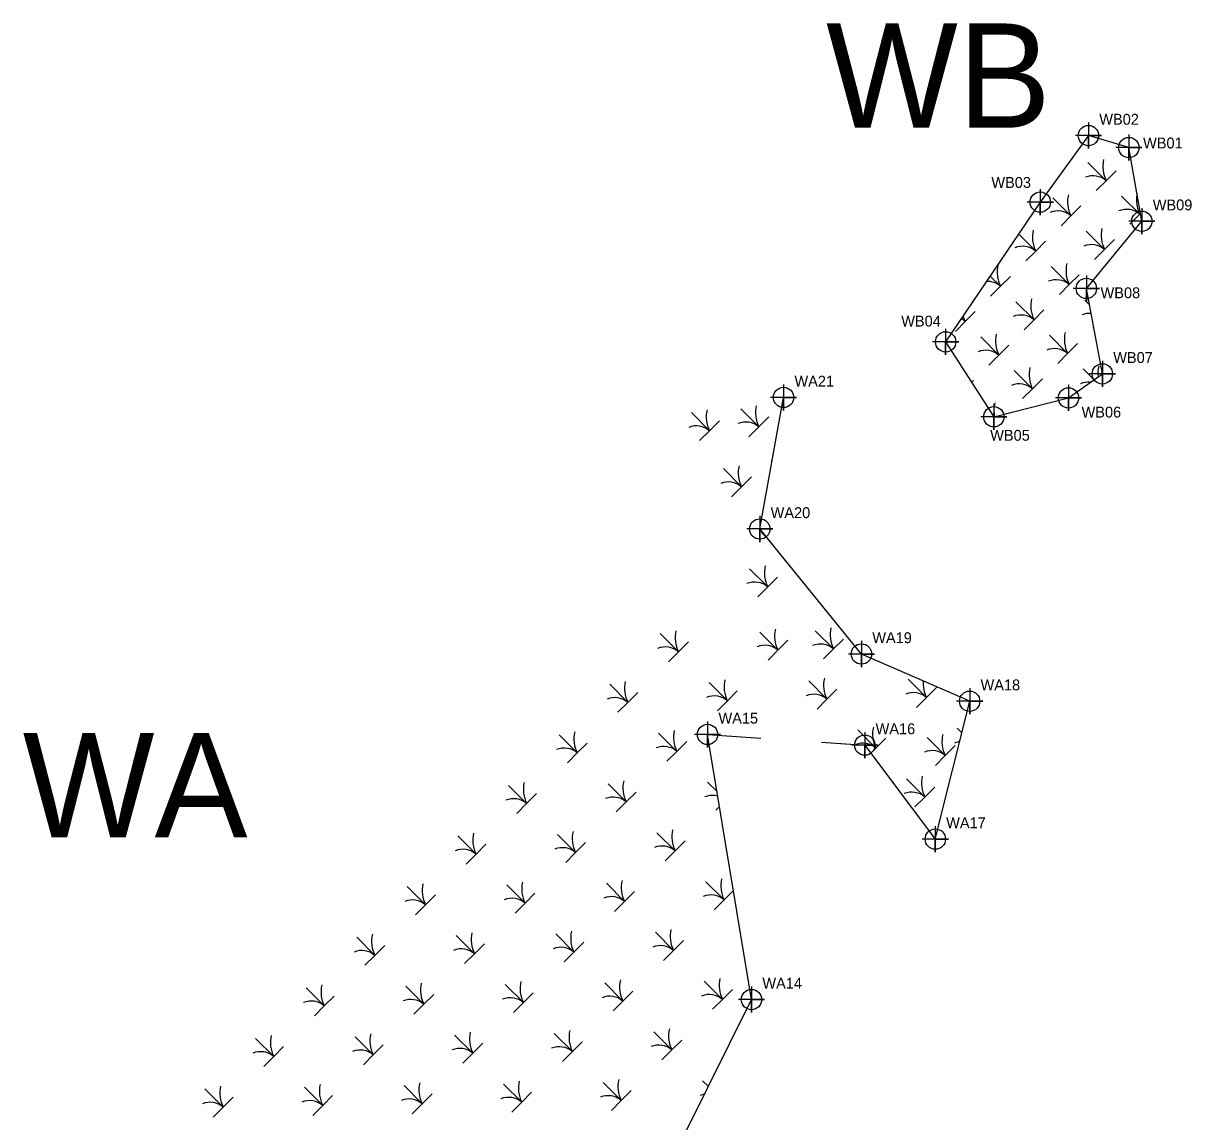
# Model space of a CAD drawing. Extents: x 2129042 to 2129395, y 148168 to 148691.
# Drawn here: x 2129065.6 to 2129334.3, y 148438.5 to 148691.1 of the extents above; entities that cross this region are included whole.
import ezdxf

# ---------------------------------------------------------------- set-up
doc = ezdxf.new("R2010")
doc.units = 0
for name, color, linetype in [('Default', 7, 'Continuous'), ('Exist Environmental Wetland Boundary', 7, 'Continuous'), ('Exist Environmental Wetland Boundary Cogo Number', 7, 'Continuous'), ('Exist Environmental Wetland Boundary Cogo Point CELL', 7, 'Continuous'), ('Exist Hydro Swamp or Marsh', 7, 'Continuous')]:
    doc.layers.add(name, color=color, linetype=linetype)

msp = doc.modelspace()

# ---------------------------------------------------------------- linework, layer by layer
at = {"layer": 'Exist Environmental Wetland Boundary'}
for points in [[(2129319.82, 148662.51), (2129310.52, 148665.27), (2129299.46, 148649.97), (2129277.7, 148617.83), (2129288.78, 148600.6), (2129305.94, 148604.95), (2129313.73, 148610.48), (2129310.05, 148630.13), (2129322.82, 148645.57), (2129319.82, 148662.51)], [(2129249.16, 148525.79), (2129259.09, 148525.12), (2129275.32, 148503.5), (2129283.22, 148535.2), (2129258.32, 148546.06), (2129234.95, 148574.81), (2129240.43, 148605.05)], [(2129099.03, 148321.24), (2129167.08, 148363.39), (2129197.64, 148395.26), (2129233.05, 148466.61), (2129222.96, 148527.56), (2129235.22, 148526.74)]]:
    msp.add_lwpolyline(points, dxfattribs=at)
at = {"layer": 'Exist Environmental Wetland Boundary Cogo Point CELL'}
for points in [[(2129310.52, 148668.27), (2129310.52, 148662.27), (2129310.52, 148665.27), (2129313.52, 148665.27), (2129307.52, 148665.27)], [(2129319.82, 148665.51), (2129319.82, 148659.51), (2129319.82, 148662.51), (2129322.82, 148662.51), (2129316.82, 148662.51)], [(2129299.46, 148652.97), (2129299.46, 148646.97), (2129299.46, 148649.97), (2129302.46, 148649.97), (2129296.46, 148649.97)], [(2129322.82, 148648.57), (2129322.82, 148642.57), (2129322.82, 148645.57), (2129325.82, 148645.57), (2129319.82, 148645.57)], [(2129310.05, 148633.13), (2129310.05, 148627.13), (2129310.05, 148630.13), (2129313.05, 148630.13), (2129307.05, 148630.13)], [(2129277.7, 148620.83), (2129277.7, 148614.83), (2129277.7, 148617.83), (2129280.7, 148617.83), (2129274.7, 148617.83)], [(2129313.73, 148613.48), (2129313.73, 148607.48), (2129313.73, 148610.48), (2129316.73, 148610.48), (2129310.73, 148610.48)], [(2129240.43, 148608.05), (2129240.43, 148602.05), (2129240.43, 148605.05), (2129243.43, 148605.05), (2129237.43, 148605.05)], [(2129305.94, 148607.95), (2129305.94, 148601.95), (2129305.94, 148604.95), (2129308.94, 148604.95), (2129302.94, 148604.95)], [(2129288.78, 148603.6), (2129288.78, 148597.6), (2129288.78, 148600.6), (2129291.78, 148600.6), (2129285.78, 148600.6)], [(2129234.95, 148577.81), (2129234.95, 148571.81), (2129234.95, 148574.81), (2129237.95, 148574.81), (2129231.95, 148574.81)], [(2129258.32, 148549.06), (2129258.32, 148543.06), (2129258.32, 148546.06), (2129261.32, 148546.06), (2129255.32, 148546.06)], [(2129283.22, 148538.2), (2129283.22, 148532.2), (2129283.22, 148535.2), (2129286.22, 148535.2), (2129280.22, 148535.2)], [(2129222.96, 148530.56), (2129222.96, 148524.56), (2129222.96, 148527.56), (2129225.96, 148527.56), (2129219.96, 148527.56)], [(2129259.09, 148528.12), (2129259.09, 148522.12), (2129259.09, 148525.12), (2129262.09, 148525.12), (2129256.09, 148525.12)], [(2129275.32, 148506.5), (2129275.32, 148500.5), (2129275.32, 148503.5), (2129278.32, 148503.5), (2129272.32, 148503.5)], [(2129233.05, 148469.61), (2129233.05, 148463.61), (2129233.05, 148466.61), (2129236.05, 148466.61), (2129230.05, 148466.61)]]:
    msp.add_lwpolyline(points, dxfattribs=at)
for centre in [(2129310.52, 148665.27), (2129319.82, 148662.51), (2129299.46, 148649.97), (2129322.82, 148645.57), (2129310.05, 148630.13), (2129277.7, 148617.83), (2129313.73, 148610.48), (2129240.43, 148605.05), (2129305.94, 148604.95), (2129288.78, 148600.6), (2129234.95, 148574.81), (2129258.32, 148546.06), (2129283.22, 148535.2), (2129222.96, 148527.56), (2129259.09, 148525.12), (2129275.32, 148503.5), (2129233.05, 148466.61)]:
    msp.add_circle(centre, 2.34, dxfattribs=at)
at = {"layer": 'Exist Hydro Swamp or Marsh'}
for p, q in [((2129311.57, 148620.99), (2129311.73, 148621.15)), ((2129283.68, 148608.54), (2129284.12, 148608.98)), ((2129237.61, 148590.44), (2129237.82, 148590.64)), ((2129224.85, 148510.14), (2129225.7, 148510.99))]:
    msp.add_line(p, q, dxfattribs=at)
for points in [[(2129312.32, 148652.62), (2129314.61, 148654.9), (2129310.42, 148659.09), (2129314.61, 148654.9), (2129316.89, 148657.18)], [(2129304.23, 148644.52), (2129306.51, 148646.8), (2129302.32, 148650.99), (2129306.51, 148646.8), (2129308.79, 148649.09)], [(2129320.04, 148644.9), (2129322.33, 148647.18), (2129318.14, 148651.37), (2129322.33, 148647.18), (2129322.5, 148647.36)], [(2129296.13, 148636.43), (2129298.41, 148638.71), (2129294.49, 148642.63)], [(2129294.49, 148642.63), (2129298.41, 148638.71), (2129300.69, 148640.99)], [(2129311.95, 148636.8), (2129314.23, 148639.08), (2129310.04, 148643.27), (2129314.23, 148639.08), (2129316.51, 148641.37)], [(2129303.85, 148628.71), (2129306.13, 148630.99), (2129301.95, 148635.17), (2129306.13, 148630.99), (2129308.41, 148633.27)], [(2129288.03, 148628.33), (2129290.31, 148630.61), (2129287.95, 148632.97)], [(2129287.95, 148632.97), (2129290.31, 148630.61), (2129292.59, 148632.89)], [(2129295.75, 148620.61), (2129298.03, 148622.89), (2129293.85, 148627.07), (2129298.03, 148622.89), (2129300.31, 148625.17)], [(2129310.75, 148626.37), (2129309.67, 148627.45), (2129310.75, 148626.37)], [(2129279.94, 148620.23), (2129282.22, 148622.51), (2129281.42, 148623.31)], [(2129281.42, 148623.31), (2129282.22, 148622.51), (2129284.5, 148624.79)], [(2129287.66, 148612.51), (2129289.94, 148614.79), (2129285.75, 148618.98), (2129289.94, 148614.79), (2129292.22, 148617.07)], [(2129303.47, 148612.89), (2129305.75, 148615.17), (2129301.57, 148619.35), (2129305.75, 148615.17), (2129308.03, 148617.45)], [(2129295.38, 148604.79), (2129297.66, 148607.07), (2129293.47, 148611.26), (2129297.66, 148607.07), (2129299.94, 148609.35)], [(2129311.81, 148609.12), (2129309.29, 148611.63), (2129311.81, 148609.12)], [(2129232.47, 148596), (2129234.75, 148598.28), (2129230.57, 148602.46), (2129234.75, 148598.28), (2129237.03, 148600.56)], [(2129221.13, 148595.12), (2129223.41, 148597.4), (2129219.22, 148601.59), (2129223.41, 148597.4), (2129225.69, 148599.68)], [(2129228.48, 148582.23), (2129230.77, 148584.51), (2129226.58, 148588.69), (2129230.77, 148584.51), (2129233.05, 148586.79)], [(2129236.74, 148572.6), (2129235.33, 148574.01), (2129236.74, 148572.6)], [(2129234.5, 148559.18), (2129236.78, 148561.47), (2129232.6, 148565.65), (2129236.78, 148561.47), (2129239.06, 148563.75)], [(2129236.86, 148544.66), (2129239.14, 148546.94), (2129234.96, 148551.12), (2129239.14, 148546.94), (2129241.42, 148549.22)], [(2129249.62, 148544.94), (2129251.9, 148547.22), (2129247.72, 148551.41), (2129251.9, 148547.22), (2129254.18, 148549.51)], [(2129213.97, 148544.28), (2129216.25, 148546.56), (2129212.07, 148550.75), (2129216.25, 148546.56), (2129218.53, 148548.84)], [(2129271, 148533.78), (2129273.28, 148536.06), (2129269.1, 148540.25), (2129273.28, 148536.06), (2129275.57, 148538.34)], [(2129202.34, 148532.65), (2129204.62, 148534.93), (2129200.44, 148539.11), (2129204.62, 148534.93), (2129206.9, 148537.21)], [(2129225.23, 148533.03), (2129227.51, 148535.31), (2129223.32, 148539.49), (2129227.51, 148535.31), (2129229.79, 148537.59)], [(2129248.12, 148533.4), (2129250.4, 148535.68), (2129246.21, 148539.87), (2129250.4, 148535.68), (2129252.68, 148537.97)], [(2129190.71, 148521.02), (2129192.99, 148523.3), (2129188.8, 148527.48), (2129192.99, 148523.3), (2129195.27, 148525.58)], [(2129213.59, 148521.39), (2129215.88, 148523.67), (2129211.69, 148527.86), (2129215.88, 148523.67), (2129218.16, 148525.96)], [(2129260.49, 148523.26), (2129261.65, 148524.43), (2129257.47, 148528.61), (2129261.65, 148524.43), (2129263.93, 148526.71)], [(2129275.33, 148520.43), (2129277.62, 148522.71), (2129273.43, 148526.9), (2129277.62, 148522.71), (2129279.9, 148525)], [(2129281.41, 148527.93), (2129280.36, 148528.99), (2129281.41, 148527.93)], [(2129179.07, 148509.38), (2129181.35, 148511.66), (2129177.17, 148515.85), (2129181.35, 148511.66), (2129183.63, 148513.95)], [(2129201.96, 148509.76), (2129204.24, 148512.04), (2129200.06, 148516.23), (2129204.24, 148512.04), (2129206.52, 148514.32)], [(2129225.14, 148514.41), (2129222.95, 148516.6), (2129225.14, 148514.41)], [(2129270.63, 148510.89), (2129272.91, 148513.17), (2129268.72, 148517.36), (2129272.91, 148513.17), (2129275.19, 148515.45)], [(2129167.44, 148497.75), (2129169.72, 148500.03), (2129165.54, 148504.22), (2129169.72, 148500.03), (2129172, 148502.31)], [(2129190.33, 148498.13), (2129192.61, 148500.41), (2129188.43, 148504.59), (2129192.61, 148500.41), (2129194.89, 148502.69)], [(2129213.22, 148498.51), (2129215.5, 148500.79), (2129211.31, 148504.97), (2129215.5, 148500.79), (2129217.78, 148503.07)], [(2129155.81, 148486.12), (2129158.09, 148488.4), (2129153.9, 148492.58), (2129158.09, 148488.4), (2129160.37, 148490.68)], [(2129178.7, 148486.5), (2129180.98, 148488.78), (2129176.79, 148492.96), (2129180.98, 148488.78), (2129183.26, 148491.06)], [(2129201.58, 148486.87), (2129203.87, 148489.15), (2129199.68, 148493.34), (2129203.87, 148489.15), (2129206.15, 148491.43)], [(2129224.47, 148487.25), (2129226.75, 148489.53), (2129222.57, 148493.71), (2129226.75, 148489.53), (2129228.9, 148491.68)], [(2129144.17, 148474.49), (2129146.46, 148476.77), (2129142.27, 148480.95), (2129146.46, 148476.77), (2129148.74, 148479.05)], [(2129167.06, 148474.86), (2129169.34, 148477.14), (2129165.16, 148481.33), (2129169.34, 148477.14), (2129171.62, 148479.42)], [(2129189.95, 148475.24), (2129192.23, 148477.52), (2129188.05, 148481.7), (2129192.23, 148477.52), (2129194.51, 148479.8)], [(2129212.84, 148475.62), (2129215.12, 148477.9), (2129210.94, 148482.08), (2129215.12, 148477.9), (2129217.4, 148480.18)], [(2129201.21, 148463.98), (2129203.49, 148466.26), (2129199.3, 148470.45), (2129203.49, 148466.26), (2129205.77, 148468.55)], [(2129224.1, 148464.36), (2129226.38, 148466.64), (2129222.19, 148470.83), (2129226.38, 148466.64), (2129228.66, 148468.92)], [(2129132.54, 148462.85), (2129134.82, 148465.13), (2129130.64, 148469.32), (2129134.82, 148465.13), (2129137.1, 148467.41)], [(2129155.43, 148463.23), (2129157.71, 148465.51), (2129153.53, 148469.69), (2129157.71, 148465.51), (2129159.99, 148467.79)], [(2129178.32, 148463.61), (2129180.6, 148465.89), (2129176.42, 148470.07), (2129180.6, 148465.89), (2129182.88, 148468.17)], [(2129120.91, 148451.22), (2129123.19, 148453.5), (2129119.01, 148457.68), (2129123.19, 148453.5), (2129125.47, 148455.78)], [(2129143.8, 148451.6), (2129146.08, 148453.88), (2129141.89, 148458.06), (2129146.08, 148453.88), (2129148.36, 148456.16)], [(2129166.69, 148451.97), (2129168.97, 148454.25), (2129164.78, 148458.44), (2129168.97, 148454.25), (2129171.25, 148456.54)], [(2129189.57, 148452.35), (2129191.86, 148454.63), (2129187.67, 148458.82), (2129191.86, 148454.63), (2129194.14, 148456.91)], [(2129212.46, 148452.73), (2129214.74, 148455.01), (2129210.56, 148459.19), (2129214.74, 148455.01), (2129217.02, 148457.29)], [(2129109.28, 148439.59), (2129111.56, 148441.87), (2129107.37, 148446.05), (2129111.56, 148441.87), (2129113.84, 148444.15)], [(2129132.16, 148439.96), (2129134.45, 148442.24), (2129130.26, 148446.43), (2129134.45, 148442.24), (2129136.73, 148444.53)], [(2129155.05, 148440.34), (2129157.33, 148442.62), (2129153.15, 148446.81), (2129157.33, 148442.62), (2129159.61, 148444.9)], [(2129177.94, 148440.72), (2129180.22, 148443), (2129176.04, 148447.18), (2129180.22, 148443), (2129182.5, 148445.28)], [(2129200.83, 148441.1), (2129203.11, 148443.38), (2129198.93, 148447.56), (2129203.11, 148443.38), (2129205.39, 148445.66)], [(2129223.13, 148446.62), (2129221.81, 148447.94), (2129223.13, 148446.62)]]:
    msp.add_lwpolyline(points, dxfattribs=at)
for centre, radius, start, end in [((2129321.05, 148658.13), 7.21, 167.1274, 206.6222), ((2129311.59, 148651.41), 4.61, 49.1403, 112.535), ((2129312.95, 148650.03), 7.21, 167.1274, 206.6222), ((2129328.77, 148650.41), 7.21, 168.5405, 206.6222), ((2129303.49, 148643.32), 4.61, 49.1403, 112.535), ((2129319.31, 148643.69), 4.61, 49.1403, 112.535), ((2129304.86, 148641.94), 7.21, 167.1274, 206.6222), ((2129320.67, 148642.31), 7.21, 167.1274, 206.6222), ((2129295.39, 148635.22), 4.61, 49.1403, 112.535), ((2129311.21, 148635.6), 4.61, 49.1403, 112.535), ((2129296.76, 148633.84), 7.21, 167.1274, 206.6222), ((2129312.58, 148634.22), 7.21, 167.1274, 206.6222), ((2129287.3, 148627.12), 4.61, 49.1403, 92.2853), ((2129303.11, 148627.5), 4.61, 49.1403, 112.535), ((2129304.48, 148626.12), 7.21, 167.1274, 206.6222), ((2129288.66, 148625.74), 7.21, 195.8506, 206.6222), ((2129295.02, 148619.4), 4.61, 49.1403, 112.535), ((2129310.83, 148619.78), 4.61, 86.3967, 112.535), ((2129279.2, 148619.02), 4.61, 49.1403, 63.0013), ((2129296.38, 148618.02), 7.21, 167.1274, 206.6222), ((2129312.2, 148618.4), 7.21, 167.1274, 206.6222), ((2129286.92, 148611.3), 4.61, 49.1403, 112.535), ((2129302.74, 148611.68), 4.61, 49.1403, 112.535), ((2129304.1, 148610.3), 7.21, 167.1274, 206.6222), ((2129319.92, 148610.68), 7.21, 167.1274, 187.0316), ((2129294.64, 148603.58), 4.61, 49.1403, 112.535), ((2129310.46, 148603.96), 4.61, 83.2801, 112.535), ((2129229.85, 148600.63), 7.21, 167.1274, 206.6222), ((2129241.19, 148601.51), 7.21, 167.1274, 206.6222), ((2129296, 148602.21), 7.21, 167.1274, 192.4505), ((2129231.73, 148594.79), 4.61, 49.1403, 112.535), ((2129220.39, 148593.91), 4.61, 49.1403, 112.535), ((2129237.21, 148587.74), 7.21, 167.1274, 206.6222), ((2129227.75, 148581.02), 4.61, 49.1403, 112.535), ((2129243.23, 148564.7), 7.21, 167.1274, 206.6222), ((2129233.76, 148557.98), 4.61, 49.1403, 112.535), ((2129222.7, 148549.79), 7.21, 167.1274, 206.6222), ((2129245.58, 148550.17), 7.21, 167.1274, 206.6222), ((2129258.35, 148550.45), 7.21, 167.1274, 206.6222), ((2129248.88, 148543.74), 4.61, 49.1403, 112.535), ((2129213.24, 148543.07), 4.61, 49.1403, 112.535), ((2129236.12, 148543.45), 4.61, 49.1403, 112.535), ((2129233.95, 148538.54), 7.21, 167.1274, 206.6222), ((2129256.84, 148538.91), 7.21, 167.1274, 206.6222), ((2129211.06, 148538.16), 7.21, 167.1274, 206.6222), ((2129279.73, 148539.29), 7.21, 175.4785, 206.6222), ((2129201.6, 148531.44), 4.61, 49.1403, 112.535), ((2129224.49, 148531.82), 4.61, 49.1403, 112.535), ((2129247.38, 148532.2), 4.61, 49.1403, 112.535), ((2129270.27, 148532.57), 4.61, 49.1403, 112.535), ((2129199.43, 148526.53), 7.21, 167.1274, 206.6222), ((2129222.32, 148526.9), 7.21, 167.1274, 206.6222), ((2129268.1, 148527.66), 7.21, 167.1274, 206.6222), ((2129284.06, 148525.94), 7.21, 167.1274, 206.6222), ((2129189.97, 148519.81), 4.61, 49.1403, 112.535), ((2129212.86, 148520.19), 4.61, 49.1403, 112.535), ((2129258.63, 148520.94), 4.61, 49.1403, 110.4105), ((2129281.52, 148521.32), 4.61, 97.7341, 112.535), ((2129274.6, 148519.23), 4.61, 49.1403, 112.535), ((2129187.8, 148514.89), 7.21, 167.1274, 206.6222), ((2129210.69, 148515.27), 7.21, 167.1274, 206.6222), ((2129279.35, 148516.4), 7.21, 167.1274, 206.6222), ((2129201.23, 148508.55), 4.61, 49.1403, 112.535), ((2129224.11, 148508.93), 4.61, 75.0038, 112.535), ((2129269.89, 148509.69), 4.61, 49.1403, 112.535), ((2129178.34, 148508.18), 4.61, 49.1403, 112.535), ((2129199.05, 148503.64), 7.21, 167.1274, 206.6222), ((2129221.94, 148504.02), 7.21, 167.1274, 206.6222), ((2129176.17, 148503.26), 7.21, 167.1274, 206.6222), ((2129166.7, 148496.54), 4.61, 49.1403, 112.535), ((2129189.59, 148496.92), 4.61, 49.1403, 112.535), ((2129212.48, 148497.3), 4.61, 49.1403, 112.535), ((2129233.2, 148492.76), 7.21, 167.1274, 206.6222), ((2129164.53, 148491.63), 7.21, 167.1274, 206.6222), ((2129187.42, 148492.01), 7.21, 167.1274, 206.6222), ((2129210.31, 148492.38), 7.21, 167.1274, 206.6222), ((2129155.07, 148484.91), 4.61, 49.1403, 112.535), ((2129177.96, 148485.29), 4.61, 49.1403, 112.535), ((2129200.85, 148485.67), 4.61, 49.1403, 112.535), ((2129223.74, 148486.04), 4.61, 49.1403, 112.535), ((2129152.9, 148480), 7.21, 167.1274, 206.6222), ((2129175.79, 148480.37), 7.21, 167.1274, 206.6222), ((2129198.68, 148480.75), 7.21, 167.1274, 206.6222), ((2129221.56, 148481.13), 7.21, 167.1274, 206.6222), ((2129166.33, 148473.66), 4.61, 49.1403, 112.535), ((2129189.22, 148474.03), 4.61, 49.1403, 112.535), ((2129212.1, 148474.41), 4.61, 49.1403, 112.535), ((2129143.44, 148473.28), 4.61, 49.1403, 112.535), ((2129164.16, 148468.74), 7.21, 167.1274, 206.6222), ((2129187.04, 148469.12), 7.21, 167.1274, 206.6222), ((2129209.93, 148469.5), 7.21, 167.1274, 206.6222), ((2129232.82, 148469.87), 7.21, 167.1274, 206.6222), ((2129141.27, 148468.36), 7.21, 167.1274, 206.6222), ((2129223.36, 148463.15), 4.61, 49.1403, 112.535), ((2129131.81, 148461.65), 4.61, 49.1403, 112.535), ((2129154.69, 148462.02), 4.61, 49.1403, 112.535), ((2129177.58, 148462.4), 4.61, 49.1403, 112.535), ((2129200.47, 148462.78), 4.61, 49.1403, 112.535), ((2129198.3, 148457.86), 7.21, 167.1274, 206.6222), ((2129221.19, 148458.24), 7.21, 167.1274, 206.6222), ((2129129.63, 148456.73), 7.21, 167.1274, 206.6222), ((2129152.52, 148457.11), 7.21, 167.1274, 206.6222), ((2129175.41, 148457.48), 7.21, 167.1274, 206.6222), ((2129120.17, 148450.01), 4.61, 49.1403, 112.535), ((2129143.06, 148450.39), 4.61, 49.1403, 112.535), ((2129165.95, 148450.77), 4.61, 49.1403, 112.535), ((2129188.84, 148451.14), 4.61, 49.1403, 112.535), ((2129211.73, 148451.52), 4.61, 49.1403, 112.535), ((2129118, 148445.1), 7.21, 167.1274, 206.6222), ((2129140.89, 148445.47), 7.21, 167.1274, 206.6222), ((2129163.78, 148445.85), 7.21, 167.1274, 206.6222), ((2129186.67, 148446.23), 7.21, 167.1274, 206.6222), ((2129209.55, 148446.61), 7.21, 167.1274, 206.6222), ((2129131.43, 148438.76), 4.61, 49.1403, 112.535), ((2129154.32, 148439.13), 4.61, 49.1403, 112.535), ((2129177.21, 148439.51), 4.61, 49.1403, 112.535), ((2129200.09, 148439.89), 4.61, 49.1403, 112.535), ((2129222.98, 148440.27), 4.61, 99.2579, 112.535), ((2129108.54, 148438.38), 4.61, 49.1403, 112.535)]:
    msp.add_arc(centre, radius, start, end, dxfattribs=at)

# ---------------------------------------------------------------- texts
at = {"layer": 'Default'}
for s, p in [('WB', (2129250.2, 148667.07)), ('WA', (2129065.48, 148503.9))]:
    msp.add_text(s, height=24, dxfattribs=at).set_placement(p)
at = {"layer": 'Exist Environmental Wetland Boundary Cogo Number'}
for s, p in [('WB02', (2129313.02, 148667.77)), ('WB01', (2129323.09, 148662.31)), ('WB03', (2129288.21, 148653.24)), ('WB09', (2129325.32, 148648.07)), ('WB08', (2129313.32, 148627.87)), ('WB04', (2129267.48, 148621.36)), ('WB07', (2129316.23, 148612.98)), ('WA21', (2129242.93, 148607.55)), ('WB06', (2129308.95, 148600.43)), ('WB05', (2129287.94, 148595.1)), ('WA20', (2129237.45, 148577.31)), ('WA19', (2129260.82, 148548.56)), ('WA18', (2129285.72, 148537.7)), ('WA15', (2129225.46, 148530.06)), ('WA16', (2129261.59, 148527.62)), ('WA17', (2129277.82, 148506)), ('WA14', (2129235.55, 148469.11))]:
    msp.add_text(s, height=2.5, dxfattribs=at).set_placement(p)

doc.saveas('drawing.dxf')
